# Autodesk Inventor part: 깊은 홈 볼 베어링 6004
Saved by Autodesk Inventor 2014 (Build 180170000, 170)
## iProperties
Created: 2026-04
Part Number: 깊은 홈 볼 베어링 6004
Material: 강철, 연강
Document SubType Name: Modeling
Designer: dg
Density: 7.86 g/cm^3
Appearance: 강철
Author: jhkim
Description: 깊은 그루브 볼 베어링
Creation Date: 2026-03-27
Sending System: Autodesk Inventor 2026
Preprocessor: ST-DEVELOPER v20.1
Author: dg
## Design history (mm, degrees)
node "깊은 홈 볼 베어링 60041"
body "Solid1"
node "Solid1_1"
node "Solid1_2"
node "Solid1_3"
node "Solid1_4"
node "Solid1_5"
node "Solid1_6"
node "Solid1_7"
node "Solid1_8"
node "Solid1_9"
node "Solid1_10"
node "기준1"
node "기준2"
node "기준3"
node "기준4"
node "기준5"
node "기준6"
node "기준7"
node "기준8"
node "기준9"
node "기준10"
node "기준11"
